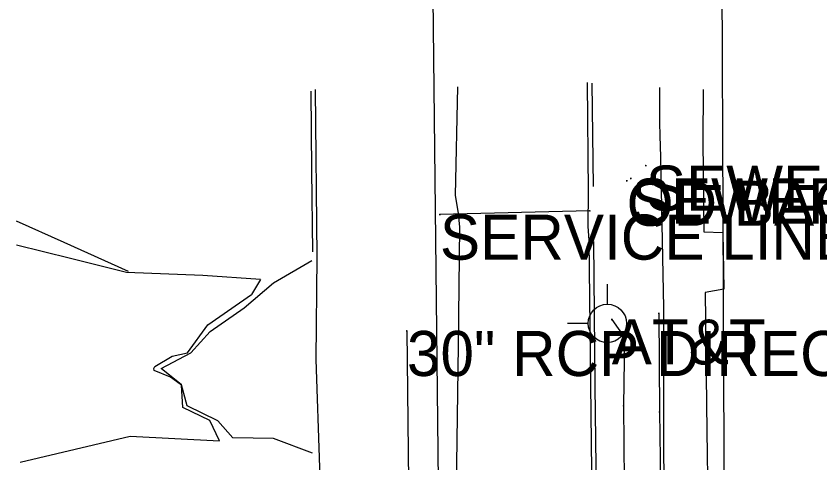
# Model space of a CAD drawing. Extents: x 1304270 to 1306561, y 1876019 to 1876752.
# Drawn here: x 1306185.4 to 1306274.6, y 1876476.9 to 1876526.4 of the extents above; entities that cross this region are included whole.
import ezdxf

# ---------------------------------------------------------------- set-up
doc = ezdxf.new("R2010")
doc.units = 0
for name, color, linetype in [('S_BUILDING', 7, 'Continuous'), ('S_CURB', 7, 'Continuous'), ('S_DRIVEWAY', 7, 'Continuous'), ('S_EDGE_PAVEMENT', 7, 'Continuous'), ('S_FIBER_OPTIC_CABLE', 7, 'Continuous'), ('S_FIBER_OPTIC_CABLE_ANNOT', 7, 'Continuous'), ('S_GAS_UTILITIES', 7, 'Continuous'), ('S_MISC_STRUCTURES_ANNOT', 7, 'Continuous'), ('S_MSC_PT_SYM', 7, 'Continuous'), ('S_PAVEMENT_CROWN', 7, 'Continuous'), ('S_SANITARY_SEWER', 7, 'Continuous'), ('S_SANITARY_SEWER_ANNOT', 7, 'Continuous'), ('S_SIDEWALK', 7, 'Continuous'), ('S_STORM_SEWER', 7, 'Continuous'), ('S_STORM_SEWER_ANNOT', 7, 'Continuous'), ('S_UTILITY_POLE', 7, 'Continuous'), ('S_UTL_PT_SYM', 7, 'Continuous')]:
    doc.layers.add(name, color=color, linetype=linetype)

msp = doc.modelspace()

# ---------------------------------------------------------------- linework, layer by layer
at = {"layer": 'S_BUILDING'}
msp.add_lwpolyline([(1306264.094, 1876452.018), (1306263.781, 1876530.368), (1306288.354, 1876530.467), (1306288.668, 1876452.116)], close=True, dxfattribs=at)
at = {"layer": 'S_CURB'}
for points in [[(1306249.322, 1876518.983), (1306249.452, 1876507.551)], [(1306218.361, 1876500.299), (1306218.229, 1876509.293), (1306218.176, 1876518.114)], [(1306249.48, 1876501.432), (1306249.657, 1876485.367), (1306249.863, 1876467.548), (1306250.046, 1876454.182)]]:
    msp.add_lwpolyline(points, dxfattribs=at)
at = {"layer": 'S_DRIVEWAY'}
for points in [[(1306185.429, 1876503.714), (1306190.717, 1876501.36), (1306197.872, 1876498.125)], [(1306212.541, 1876497.225), (1306206.139, 1876497.646), (1306197.683, 1876497.988), (1306191.458, 1876499.536), (1306185.477, 1876501.024)], [(1306218.313, 1876477.936), (1306213.972, 1876479.568), (1306209.47, 1876479.645), (1306207.823, 1876481.527), (1306204.42, 1876483.207), (1306203.795, 1876485.529), (1306201.52, 1876487.361), (1306204.825, 1876489.076), (1306206.965, 1876491.457), (1306210.734, 1876494.066), (1306213.971, 1876496.835), (1306218.235, 1876499.318)], [(1306212.541, 1876497.225), (1306211.535, 1876495.534)], [(1306185.875, 1876476.954), (1306198.094, 1876479.834), (1306208.009, 1876479.328), (1306206.939, 1876481.592), (1306203.942, 1876483.002), (1306203.784, 1876485.508), (1306202.575, 1876486.391), (1306200.751, 1876487.132), (1306200.698, 1876487.346), (1306200.834, 1876487.56), (1306202.735, 1876488.725), (1306204.466, 1876489.08), (1306206.712, 1876492.201), (1306211.535, 1876495.534)]]:
    msp.add_lwpolyline(points, dxfattribs=at)
at = {"layer": 'S_EDGE_PAVEMENT'}
for points in [[(1306218.613, 1876518.304), (1306218.815, 1876499.726), (1306218.673, 1876488.347), (1306219.095, 1876476.375), (1306219.343, 1876459.757), (1306219.591, 1876443.139), (1306219.567, 1876442.038), (1306219.458, 1876440.95), (1306219.294, 1876439.841), (1306218.914, 1876438.908), (1306218.403, 1876437.649), (1306217.811, 1876436.787), (1306217.079, 1876435.809), (1306216.471, 1876435.049), (1306215.881, 1876434.409)], [(1306248.783, 1876519.057), (1306248.898, 1876506.935), (1306248.86, 1876503.149), (1306248.986, 1876501.531), (1306249.131, 1876488.738), (1306249.277, 1876475.946), (1306249.566, 1876454.083), (1306249.631, 1876449.278), (1306250.855, 1876444.885), (1306251.569, 1876442.168), (1306253.793, 1876438.82), (1306254.52, 1876438.546), (1306256.554, 1876437.075), (1306259.309, 1876434.252), (1306261.215, 1876432.508)]]:
    msp.add_lwpolyline(points, dxfattribs=at)
at = {"layer": 'S_FIBER_OPTIC_CABLE'}
for p, q in [((1306251.508, 1876492.797), (1306252.917, 1876490.791)), ((1306252.917, 1876490.791), (1306252.837, 1876483.205)), ((1306252.837, 1876483.205), (1306252.953, 1876469.669))]:
    msp.add_line(p, q, dxfattribs=at)
at = {"layer": 'S_GAS_UTILITIES'}
for p, q in [((1306256.739, 1876493.453), (1306256.812, 1876482.524)), ((1306256.812, 1876482.524), (1306257.063, 1876466.432))]:
    msp.add_line(p, q, dxfattribs=at)
at = {"layer": 'S_MSC_PT_SYM'}
for points in [[(1306255.296, 1876509.853), (1306255.296, 1876509.903), (1306255.296, 1876509.853), (1306255.246, 1876509.853), (1306255.296, 1876509.853), (1306255.296, 1876509.803), (1306255.296, 1876509.853), (1306255.346, 1876509.853)], [(1306253.62, 1876508.427), (1306253.62, 1876508.477), (1306253.62, 1876508.427), (1306253.57, 1876508.427), (1306253.62, 1876508.427), (1306253.62, 1876508.377), (1306253.62, 1876508.427), (1306253.67, 1876508.427)]]:
    msp.add_lwpolyline(points, dxfattribs=at)
at = {"layer": 'S_PAVEMENT_CROWN'}
msp.add_lwpolyline([(1306234.388, 1876518.594), (1306234.152, 1876506.545), (1306234.488, 1876504.577), (1306234.64, 1876503.04), (1306234.47, 1876489.897), (1306234.3, 1876476.755), (1306234.741, 1876459.131), (1306235.181, 1876441.507), (1306234.88, 1876434.411)], dxfattribs=at)
at = {"layer": 'S_SANITARY_SEWER'}
for p, q in [((1306230.819, 1876604.437), (1306232.633, 1876441.82)), ((1306249.084, 1876504.836), (1306232.453, 1876504.415))]:
    msp.add_line(p, q, dxfattribs=at)
at = {"layer": 'S_SIDEWALK'}
for points in [[(1306256.799, 1876518.519), (1306256.797, 1876514.623), (1306256.85, 1876513.159), (1306256.913, 1876510.826), (1306257.244, 1876494.088), (1306257.265, 1876478.09), (1306257.431, 1876464.961), (1306257.646, 1876445.741)], [(1306261.648, 1876518.279), (1306261.616, 1876512.546), (1306261.722, 1876502.517), (1306263.833, 1876502.428), (1306263.959, 1876496.138), (1306261.863, 1876495.791), (1306262.072, 1876480.394), (1306262.281, 1876464.997), (1306262.548, 1876445.574)]]:
    msp.add_lwpolyline(points, dxfattribs=at)
at = {"layer": 'S_STORM_SEWER'}
msp.add_line((1306228.792, 1876491.508), (1306229.409, 1876435.331), dxfattribs=at)
at = {"layer": 'S_UTILITY_POLE'}
for p, q in [((1306251.029, 1876494.456), (1306251.029, 1876496.704)), ((1306248.937, 1876492.325), (1306246.612, 1876492.325)), ((1306251.107, 1876487.907), (1306251.107, 1876490.232))]:
    msp.add_line(p, q, dxfattribs=at)
msp.add_circle((1306251.032, 1876492.346), 2.128, dxfattribs=at)
at = {"layer": 'S_UTL_PT_SYM'}
for points in [[(1306253.175, 1876508.17), (1306253.175, 1876508.22), (1306253.175, 1876508.17), (1306253.125, 1876508.17), (1306253.175, 1876508.17), (1306253.175, 1876508.12), (1306253.175, 1876508.17), (1306253.225, 1876508.17)], [(1306249.084, 1876504.836), (1306249.084, 1876504.886), (1306249.084, 1876504.836), (1306249.034, 1876504.836), (1306249.084, 1876504.836), (1306249.084, 1876504.786), (1306249.084, 1876504.836), (1306249.134, 1876504.836)], [(1306232.453, 1876504.415), (1306232.453, 1876504.465), (1306232.453, 1876504.415), (1306232.403, 1876504.415), (1306232.453, 1876504.415), (1306232.453, 1876504.365), (1306232.453, 1876504.415), (1306232.503, 1876504.415)], [(1306256.739, 1876493.453), (1306256.739, 1876493.503), (1306256.739, 1876493.453), (1306256.689, 1876493.453), (1306256.739, 1876493.453), (1306256.739, 1876493.403), (1306256.739, 1876493.453), (1306256.789, 1876493.453)], [(1306251.508, 1876492.797), (1306251.508, 1876492.847), (1306251.508, 1876492.797), (1306251.458, 1876492.797), (1306251.508, 1876492.797), (1306251.508, 1876492.747), (1306251.508, 1876492.797), (1306251.558, 1876492.797)], [(1306228.792, 1876491.508), (1306228.792, 1876491.558), (1306228.792, 1876491.508), (1306228.742, 1876491.508), (1306228.792, 1876491.508), (1306228.792, 1876491.458), (1306228.792, 1876491.508), (1306228.842, 1876491.508)], [(1306252.917, 1876490.791), (1306252.917, 1876490.841), (1306252.917, 1876490.791), (1306252.867, 1876490.791), (1306252.917, 1876490.791), (1306252.917, 1876490.741), (1306252.917, 1876490.791), (1306252.967, 1876490.791)], [(1306252.837, 1876483.205), (1306252.837, 1876483.255), (1306252.837, 1876483.205), (1306252.787, 1876483.205), (1306252.837, 1876483.205), (1306252.837, 1876483.155), (1306252.837, 1876483.205), (1306252.887, 1876483.205)], [(1306256.812, 1876482.524), (1306256.812, 1876482.574), (1306256.812, 1876482.524), (1306256.762, 1876482.524), (1306256.812, 1876482.524), (1306256.812, 1876482.474), (1306256.812, 1876482.524), (1306256.862, 1876482.524)]]:
    msp.add_lwpolyline(points, dxfattribs=at)

# ---------------------------------------------------------------- texts
at = {"layer": 'S_FIBER_OPTIC_CABLE_ANNOT'}
msp.add_text('AT&T', height=5, dxfattribs=at).set_placement((1306251.508, 1876487.797))
at = {"layer": 'S_MISC_STRUCTURES_ANNOT'}
for s, p in [('SEWER CLEAN OUT', (1306255.296, 1876504.853)), ('SEWER CLEN OUT', (1306253.62, 1876503.427))]:
    msp.add_text(s, height=5, dxfattribs=at).set_placement(p)
at = {"layer": 'S_SANITARY_SEWER_ANNOT'}
for s, p in [('OD BACK/ADD FG IF NEEDED', (1306253.175, 1876503.17)), ('SERVICE LINE', (1306232.453, 1876499.415))]:
    msp.add_text(s, height=5, dxfattribs=at).set_placement(p)
at = {"layer": 'S_STORM_SEWER_ANNOT'}
msp.add_text('30" RCP DIRECTION ONLY', height=5, dxfattribs=at).set_placement((1306228.792, 1876486.508))

doc.saveas('drawing.dxf')
